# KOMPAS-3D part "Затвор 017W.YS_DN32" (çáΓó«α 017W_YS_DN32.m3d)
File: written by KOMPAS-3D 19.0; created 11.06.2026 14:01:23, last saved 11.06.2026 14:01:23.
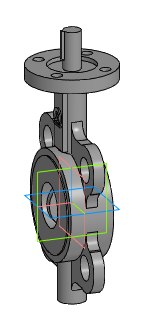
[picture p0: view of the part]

Document properties: Автор: Евгений; Полное имя файла: Z:\3.Личные\kachalov\001_3d для проектировщиков\x.x Тип 017W.Y(S) Затвор дисковый поворотный межфланцевый\_stp_Затвор 017W.YS_DN32-DN1200\Затвор 017W_YS_DN32.m3d

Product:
- Part/product: Затвор 017W.YS_DN32

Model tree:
1. Операция без истории:1  (labels: Затвор 017W.YS_DN32)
